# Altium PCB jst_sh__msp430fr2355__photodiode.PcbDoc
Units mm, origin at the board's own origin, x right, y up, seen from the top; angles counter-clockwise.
Board outline 56 x 30 mm, 2 copper layers (Top, Bottom), stack 0 mm thick; 17 components, 9 nets, 93 pads, 27 vias.
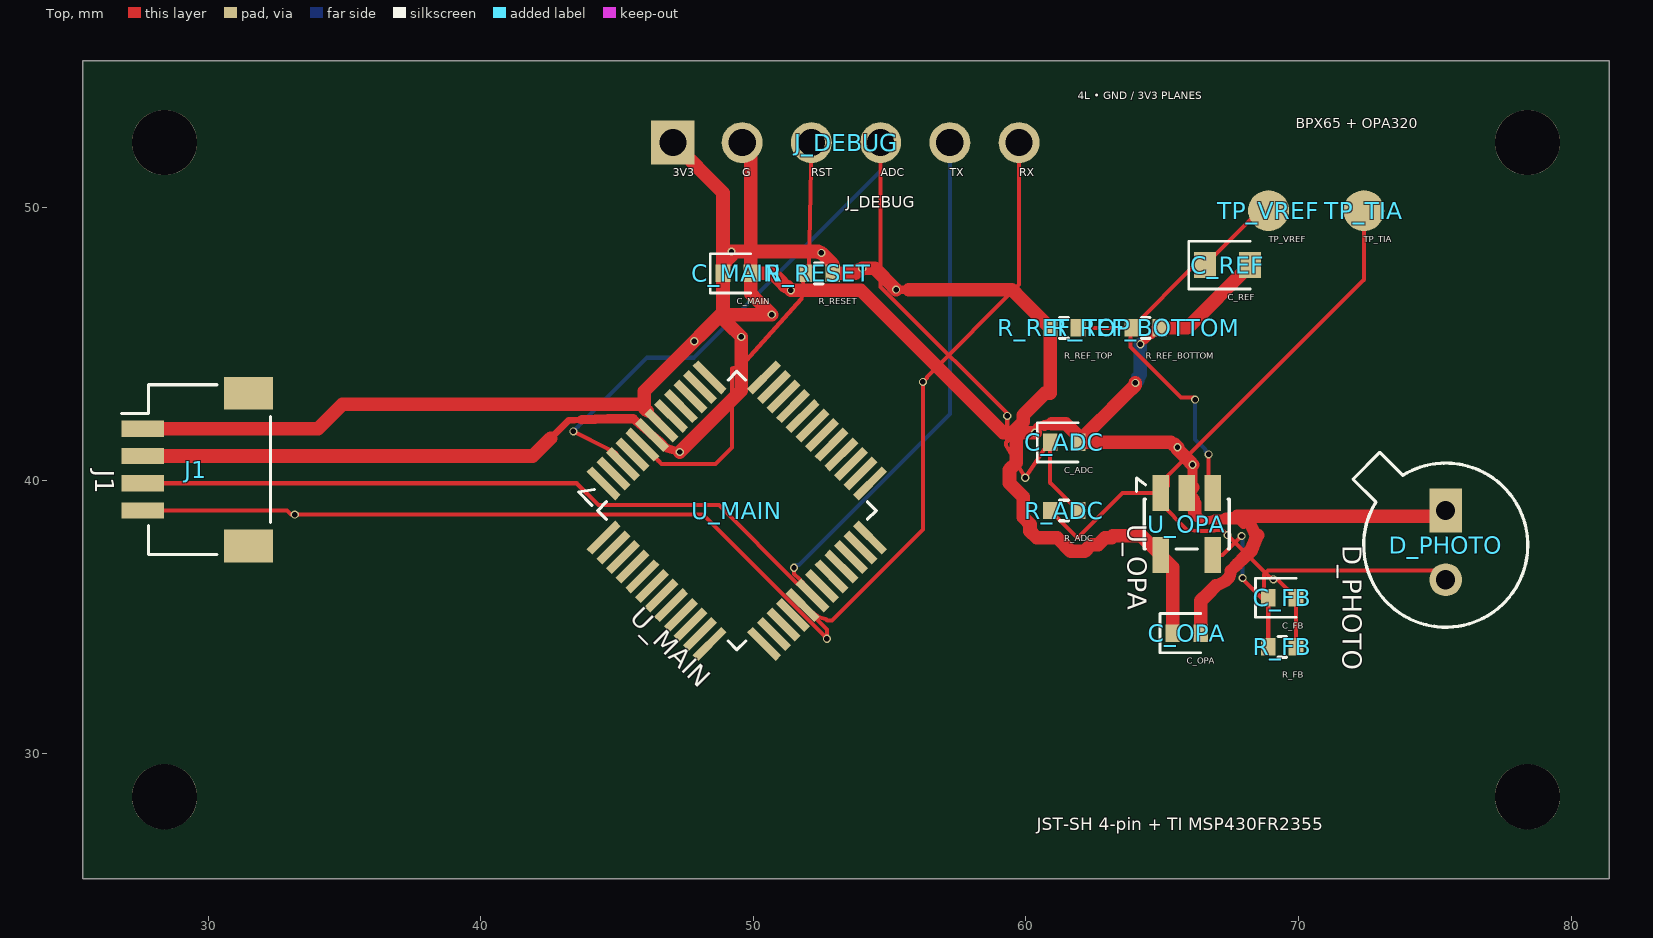
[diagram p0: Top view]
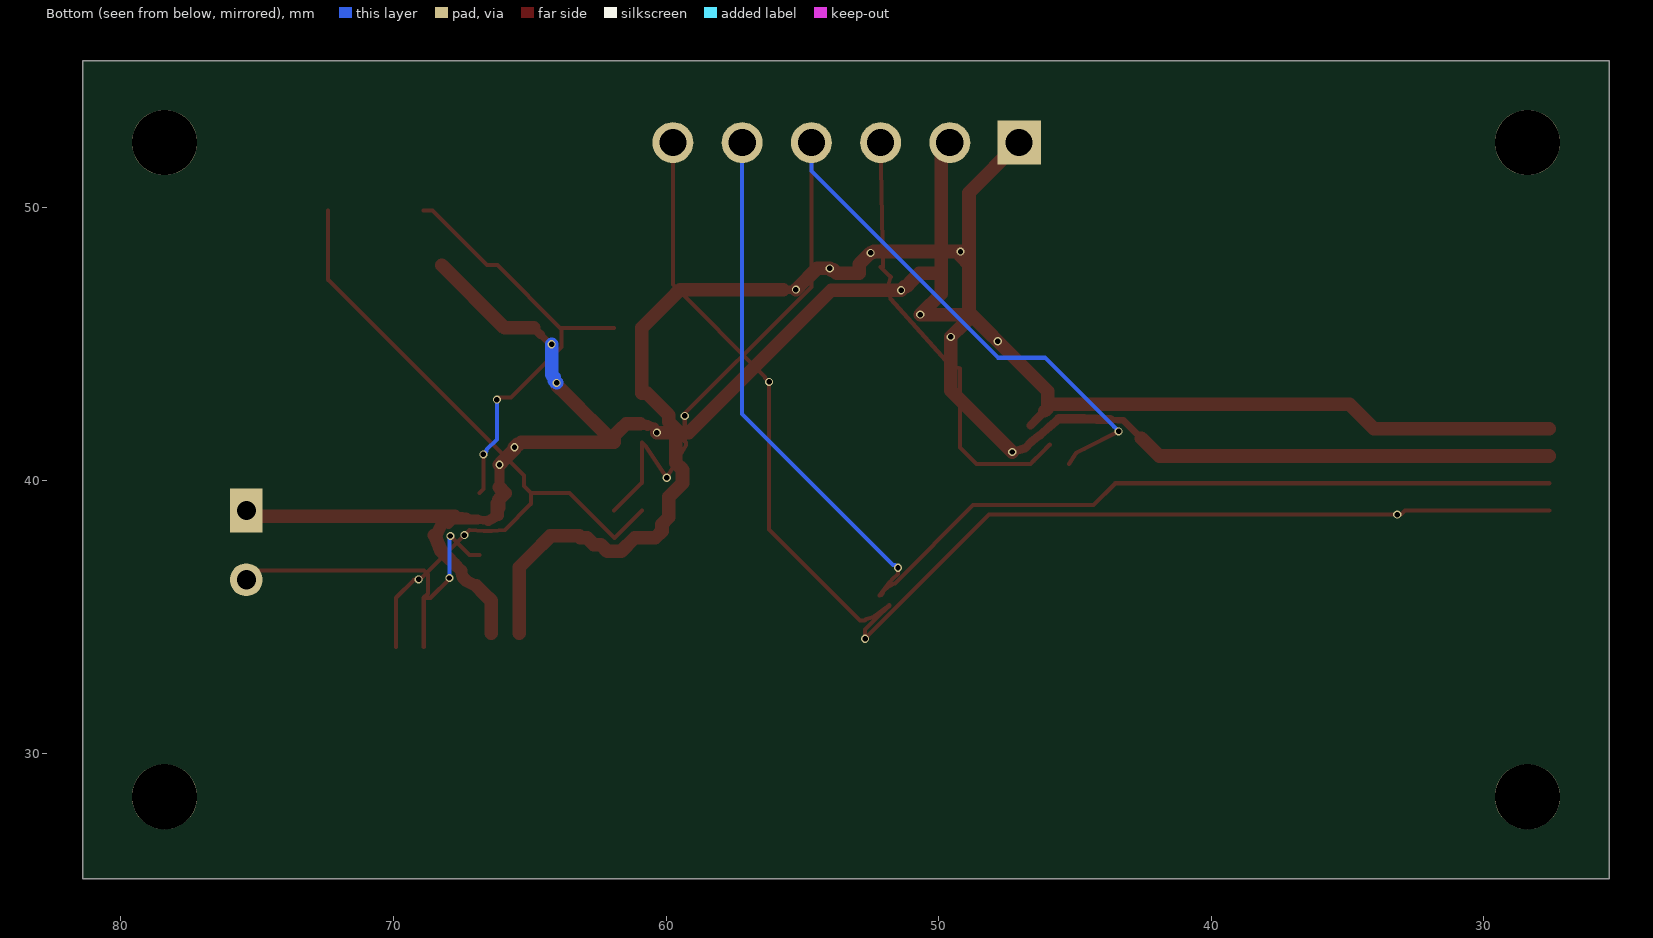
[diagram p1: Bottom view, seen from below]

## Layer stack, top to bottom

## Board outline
25.4,55.4 81.4,55.4 81.4,25.4 25.4,25.4

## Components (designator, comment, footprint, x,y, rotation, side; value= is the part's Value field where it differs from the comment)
C_ADC "" TSCIRCUIT-1.5600x0.6400mm 61.4,41.4 r0 top
C_FB "" TSCIRCUIT-1.5600x0.6400mm 69.4,35.7 r0 top
C_MAIN "" TSCIRCUIT-1.5600x0.6400mm 49.4,47.6 r0 top
C_OPA "" TSCIRCUIT-1.5600x0.6400mm 65.9,34.4 r0 top
C_REF "" TSCIRCUIT-2.4500x0.9500mm 67.4,47.9 r0 top
D_PHOTO "" TSCIRCUIT-1.2000x3.9400mm 75.4,37.73 r270 top
J1 "" TSCIRCUIT-5.5500x6.8000mm 29.6,40.4 r270 top
J_DEBUG "" TSCIRCUIT-14.2000x1.5000mm 53.4,52.4 r0 top
R_ADC "" TSCIRCUIT-1.5600x0.6400mm 61.4,38.9 r0 top
R_FB "" TSCIRCUIT-1.5600x0.6400mm 69.4,33.9 r0 top
R_REF_BOTTOM "" TSCIRCUIT-1.5600x0.6400mm 64.4,45.6 r0 top
R_REF_TOP "" TSCIRCUIT-1.5600x0.6400mm 61.4,45.6 r0 top
R_RESET "" TSCIRCUIT-1.5600x0.6400mm 52.4,47.6 r0 top
TP_TIA "" TSCIRCUIT-1.5000x1.5000mm 72.4,49.9 r0 top
TP_VREF "" TSCIRCUIT-1.5000x1.5000mm 68.9,49.9 r0 top
U_MAIN "" TSCIRCUIT-11.0309x11.0309mm 49.4,38.9 r315 top
U_OPA "" TSCIRCUIT-2.5000x3.6000mm 65.9,38.4 r270 top

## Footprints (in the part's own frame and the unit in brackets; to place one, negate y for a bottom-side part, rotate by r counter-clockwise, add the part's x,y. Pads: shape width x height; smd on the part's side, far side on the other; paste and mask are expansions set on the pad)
TSCIRCUIT-1.2000x3.9400mm [mm]
  rect 1.6x1.2 hole 0.7: 1(-1.17,0)
  round 1.2 hole 0.7: 2(1.37,0)
  silkscreen extent -3.3,-3.4 3.11,3.01
TSCIRCUIT-1.5000x1.5000mm [mm]
  round 1.5 smd: 1(0,0)
TSCIRCUIT-1.5600x0.6400mm [mm]
  rect 0.54x0.64 smd: 1(-0.51,0) 2(0.51,0)
  silkscreen extent -0.98,-0.72 0.51,0.72
TSCIRCUIT-2.4500x0.9500mm [mm]
  rect 0.8x0.95 smd: 1(-0.825,0) 2(0.825,0)
  silkscreen extent -1.43,-0.87 0.82,0.87
TSCIRCUIT-2.5000x3.6000mm [mm]
  rect 1.325x0.6 smd: 1(-1.138,-0.95) 2(-1.138,0) 3(-1.138,0.95) 4(1.137,0.95) 5(1.137,-0.95)
  silkscreen extent -1.69,-1.84 0.91,1.56
TSCIRCUIT-5.5500x6.8000mm [mm]
  rect 1.2x1.8 smd: 1(-2.8,1.875) 1(2.8,1.875)
  rect 0.6x1.55 smd: 1(-1.5,-2) 2(-0.5,-2) 3(0.5,-2) 4(1.5,-2)
  silkscreen extent -3.11,-2.77 3.11,2.69
TSCIRCUIT-11.0309x11.0309mm [mm]
  rect 1.475x0.3 smd: 1(-4.162,-2.75) 2(-4.162,-2.25) 3(-4.162,-1.75) 4(-4.162,-1.25) 5(-4.162,-0.75) 6(-4.162,-0.25) 7(-4.162,0.25) 8(-4.162,0.75) 9(-4.162,1.25) 10(-4.162,1.75) 11(-4.162,2.25) 12(-4.162,2.75) 25(4.162,2.75) 26(4.162,2.25) 27(4.163,1.75) 28(4.163,1.25) 29(4.162,0.75) 30(4.162,0.25) 31(4.163,-0.25) 32(4.163,-0.75) 33(4.162,-1.25) 34(4.162,-1.75) 35(4.163,-2.25) 36(4.163,-2.75)
  rect 0.3x1.475 smd: 13(-2.75,4.162) 14(-2.25,4.162) 15(-1.75,4.162) 16(-1.25,4.162) 17(-0.75,4.162) 18(-0.25,4.162) 19(0.25,4.162) 20(0.75,4.162) 21(1.25,4.162) 22(1.75,4.162) 23(2.25,4.162) 24(2.75,4.162) 37(2.75,-4.163) 38(2.25,-4.163) 39(1.75,-4.162) 40(1.25,-4.163) 41(0.75,-4.163) 42(0.25,-4.163) 43(-0.25,-4.162) 44(-0.75,-4.163) 45(-1.25,-4.163) 46(-1.75,-4.163) 47(-2.25,-4.162) 48(-2.75,-4.163)
  silkscreen extent -4.59,-3.63 3.61,3.61
TSCIRCUIT-14.2000x1.5000mm [mm]
  rect 1.6x1.6 hole 1: 1(-6.35,0)
  round 1.5 hole 1: 2(-3.81,0) 3(-1.27,0) 4(1.27,0) 5(3.81,0) 6(6.35,0)

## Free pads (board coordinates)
  round 2.4 hole 2.4 unplated: NPTH-1(28.4,28.4) NPTH-2(78.4,52.4) NPTH-3(78.4,28.4) NPTH-4(28.4,52.4)

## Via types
v1: diameter 0.3, hole 0.2, Top to Bottom, 27 vias

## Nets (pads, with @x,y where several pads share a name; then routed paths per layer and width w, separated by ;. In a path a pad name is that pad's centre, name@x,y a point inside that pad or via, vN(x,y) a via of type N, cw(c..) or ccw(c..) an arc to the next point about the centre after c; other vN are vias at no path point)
ADC_IN: C_ADC.1 J_DEBUG.4 R_ADC.2 U_MAIN.3 | length 37.5
  Top w0.15: v1(43.4,41.8) 44.658,41.162 44.953,41.015 U_MAIN.3 ; J_DEBUG.4 54.67,47.099 55.341,46.428 55.347,46.428 59.359,42.415 v1(59.315,42.371) 59.315,41.442 59.266,41.393 59.266,41.306 v1(59.975,40.1) 60.75,41.26 C_ADC.1 60.89,39.92 R_ADC.2
  Bottom w0.15: v1(43.4,41.8) 43.558,41.958 46.105,44.505 47.827,44.505 54.67,51.349 J_DEBUG.4
GND: C_ADC.2 C_MAIN.2 C_OPA.2 C_REF.2 D_PHOTO.1 J1.1@27.6,41.9 J_DEBUG.2 R_REF_BOTTOM.2 U_MAIN.7 U_OPA.2 | length 82.7
  Top w0.25: v1(64.2,45) 64.311,45.111 64.363,45.111 64.607,45.355
  Top w0.3: U_MAIN.7@46.373,42.282 U_MAIN.7
  Top w0.305: U_MAIN.7@46.114,42.544 U_MAIN.7@46.373,42.282
  Top w0.308: U_MAIN.7@46.115,42.544 46.353,42.304 U_MAIN.7
  Top w0.325: v1(60.337,41.759) 60.431,41.962 ; 64.607,45.355 R_REF_BOTTOM.2@64.852,45.6 ; 66.922,38.575 66.525,38.525 66.932,38.579 67.339,38.633
  Top w0.35: 60.431,41.962 60.688,42.024 ; U_OPA.2@66.111,39.749 66.111,40.162 v1(66.111,40.576)
  Top w0.375: U_OPA.2 66.079,39.358 66.258,39.179 66.258,38.687 66.525,38.525 66.15,38.713 ; 66.922,38.575 67.816,38.575 67.986,38.405 68.213,38.431
  Top w0.4: 60.688,42.024 60.944,42.086 ; U_OPA.2@66.138,39.012 66.15,38.713 ; 67.339,38.633 67.747,38.687
  Top w0.45: 46,42.8 46.072,42.587 U_MAIN.7@46.115,42.544 ; 66.964,36.138 67.327,36.317 67.473,36.463 67.517,36.691 67.764,36.938 ; 68.213,38.431 68.4,38.056
  Top w0.475: 45.85,42.803 45.853,42.806 46.113,42.544 ; 67.764,36.938 68.01,37.184 ; 68.4,38.056 68.494,37.994
  Top w0.5: J1.1@27.6,41.9 28.095,41.9 28.589,41.9 29.084,41.9 29.579,41.9 30.073,41.9 30.568,41.9 31.063,41.9 31.558,41.9 32.052,41.9 32.547,41.9 33.042,41.9 33.536,41.9 34.031,41.9 34.931,42.8 43.341,42.8 45.51,42.8 45.513,42.803 45.85,42.803 ; 46,42.8 46,43 46,43.276 v1(47.831,45.107) 47.832,45.108 48.158,45.434 48.485,45.761 48.811,46.087 49.277,46.087 49.742,46.087 50.208,46.087 v1(50.674,46.087) 50.619,46.142 50.619,46.144 50.382,46.38 50.146,46.616 49.91,46.852 49.91,47.226 C_MAIN.2 ; J_DEBUG.2 49.91,52.08 C_MAIN.2 ; v1(60.337,41.759) 59.166,41.759 59.025,41.9 53.943,46.982 v1(51.38,46.982) 51.259,47.103 51.204,47.103 50.956,47.352 50.707,47.6 50.309,47.6 C_MAIN.2 ; 60.944,42.086 61.224,42.086 61.464,42.086 61.65,41.9 61.91,41.64 C_ADC.2 ; v1(64.016,43.583) 64.016,43.506 63.665,43.155 63.314,42.804 62.963,42.453 62.612,42.102 62.261,41.751 C_ADC.2 ; R_REF_BOTTOM.2@64.852,45.6 R_REF_BOTTOM.2 65.925,45.6 C_REF.2 ; U_OPA.2@66.111,39.749 U_OPA.2 66.138,39.3 U_OPA.2@66.138,39.012 ; v1(66.111,40.576) 66.037,40.65 66.037,40.672 65.799,40.91 65.561,41.148 v1(65.561,41.224) 65.452,41.333 65.382,41.333 65.315,41.4 64.829,41.4 64.342,41.4 63.856,41.4 63.369,41.4 62.883,41.4 62.396,41.4 C_ADC.2 ; C_OPA.2 66.41,34.795 66.41,35.189 66.41,35.584 66.687,35.861 66.964,36.138 ; 67.747,38.687 68.243,38.687 68.739,38.687 69.235,38.687 69.731,38.687 70.227,38.687 70.723,38.687 71.219,38.687 71.715,38.687 72.211,38.687 72.707,38.687 73.203,38.687 73.699,38.687 74.195,38.687 74.691,38.687 75.187,38.687 D_PHOTO.1 ; 68.01,37.184 68.257,37.431 68.375,37.712 68.494,37.994
  Bottom w0.5: v1(64.016,43.583) 64.103,43.67 64.103,43.791 64.2,43.888 64.2,44.258 64.2,44.629 v1(64.2,45)
MAIN_RESET: J_DEBUG.3 R_RESET.1 U_MAIN.5 | length 16.4
  Top w0.15: U_MAIN.5 46.24,40.999 46.512,40.727 46.629,40.61 46.712,40.61 48.613,40.61 49.213,41.21 49.213,44.11 49.575,44.225 51.758,46.655 51.887,47.054 51.758,47.468 R_RESET.1 52.13,47.84 52.05,47.825 J_DEBUG.3
PD_SUM: C_FB.1 D_PHOTO.2 R_FB.1 U_OPA.4 | length 13.8
  Top w0.15: U_OPA.4 67.208,37.262 v1(67.911,37.965) ; v1(67.95,36.425) 67.941,36.416 67.941,36.395 68.636,35.7 C_FB.1 ; R_FB.1 C_FB.1 ; D_PHOTO.2 75.059,36.701 75.042,36.701 68.88,36.701 68.736,36.558 68.736,35.854 C_FB.1
  Bottom w0.15: v1(67.911,37.965) 67.92,37.956 67.92,37.911 67.95,37.881 v1(67.95,36.425)
TIA_OUT: C_FB.2 R_ADC.1 R_FB.2 TP_TIA.1 U_OPA.1 | length 27.2
  Top w0.15: R_ADC.1 61.896,37.894 63.539,39.538 U_OPA.1 ; R_FB.2 C_FB.2 69.238,36.372 v1(69.08,36.372) 69.005,36.447 68.953,36.447 v1(67.4,38) 67.354,38.046 67.214,38.186 66.681,38.146 66.411,38.15 65.913,38.186 64.95,39.149 U_OPA.1 ; TP_TIA.1 72.4,47.367 65.212,40.178 65.212,39.799 U_OPA.1
UART_MAIN_RX: J1.4 J_DEBUG.6 U_MAIN.32 | length 50.3
  Top w0.15: J1.4 32.888,38.9 33.038,38.75 v1(33.175,38.75) 48.157,38.75 52.616,34.29 52.616,34.277 v1(52.698,34.195) 52.698,34.542 52.414,34.826 52.303,34.936 52.127,35.113 51.972,35.26 51.937,35.286 51.897,35.324 51.825,35.375 U_MAIN.32 52.441,34.976 52.657,34.919 52.714,34.863 52.882,34.863 56.221,38.201 v1(56.221,43.617) 56.365,43.761 56.365,43.802 59.75,47.188 J_DEBUG.6
UART_MAIN_TX: J1.3 J_DEBUG.5 U_MAIN.31 | length 45.6
  Top w0.15: J1.3 43.521,39.9 44.325,39.096 48.744,39.096 51.61,36.23 51.853,36.1 52.024,35.942 52.041,35.899 52.059,35.853 52.1,35.8 U_MAIN.31 51.794,36.277 51.688,36.382 51.493,36.578 v1(51.493,36.8)
  Bottom w0.15: v1(51.493,36.8) 51.6,36.907 51.676,36.907 57.21,42.441 J_DEBUG.5
VCC_3V3: C_MAIN.1 C_OPA.1 J1.2 J_DEBUG.1 R_REF_TOP.1 R_RESET.2 U_MAIN.6 U_OPA.5 | length 65.3
  Top w0.25: 42.564,41.553 42.891,41.879 43.217,42.205 43.71,42.229
  Top w0.3: U_MAIN.6@45.934,41.971 U_MAIN.6
  Top w0.312: 45.588,42.275 U_MAIN.6@45.934,41.971 ; U_MAIN.6 46.593,41.431 46.838,41.181 v1(47.301,41.046) ; v1(55.236,47.004) 55.708,47.004
  Top w0.35: 43.71,42.229 44.203,42.254 44.664,42.261 45.126,42.268 45.588,42.275
  Top w0.5: J1.2 28.094,40.9 28.587,40.9 29.081,40.9 29.574,40.9 30.068,40.9 30.561,40.9 31.055,40.9 31.548,40.9 32.042,40.9 32.535,40.9 33.029,40.9 33.522,40.9 34.016,40.9 34.509,40.9 35.003,40.9 35.496,40.9 35.99,40.9 36.483,40.9 36.977,40.9 37.47,40.9 37.964,40.9 38.457,40.9 38.951,40.9 39.444,40.9 39.938,40.9 40.431,40.9 40.925,40.9 41.418,40.9 41.912,40.9 42.238,41.226 42.564,41.553 ; J_DEBUG.1 48.89,50.56 C_MAIN.1 ; v1(47.301,41.046) 47.311,41.056 47.632,41.377 47.953,41.698 48.273,42.018 48.594,42.339 48.915,42.66 49.236,42.981 49.557,43.302 49.557,43.794 49.557,44.285 49.557,44.777 v1(49.557,45.269) 49.481,45.345 49.185,45.641 48.89,45.936 48.89,46.352 48.89,46.768 48.89,47.184 C_MAIN.1 ; v1(55.236,47.004) 55.192,47.048 54.948,47.292 54.703,47.537 54.459,47.781 v1(53.998,47.781) 53.942,47.725 53.858,47.725 53.734,47.6 53.322,47.6 R_RESET.2 52.91,47.94 v1(52.497,48.353) 52.493,48.356 52.431,48.356 52.387,48.4 51.932,48.4 51.477,48.4 51.021,48.4 50.566,48.4 50.111,48.4 49.655,48.4 v1(49.2,48.4) 49.187,48.387 49.187,48.227 48.89,47.93 C_MAIN.1 ; 55.708,47.004 56.18,47.004 56.653,47.004 57.125,47.004 57.597,47.004 58.069,47.004 58.542,47.004 59.014,47.004 59.486,47.004 59.837,46.653 60.188,46.302 60.539,45.951 R_REF_TOP.1 60.89,43.213 60.713,43.213 59.9,42.4 59.9,42.15 59.65,41.9 59.65,40.65 59.4,40.4 59.4,39.9 59.9,39.4 59.9,38.65 60.15,38.4 60.15,38.15 60.4,37.9 61.15,37.9 61.65,37.4 62.15,37.4 62.4,37.65 62.65,37.65 62.9,37.9 63.15,37.9 63.15,37.933 63.185,37.968 64.244,37.968 U_OPA.5 65.39,36.822 C_OPA.1
VREF_0V5: C_REF.1 R_REF_BOTTOM.1 R_REF_TOP.2 TP_VREF.1 U_OPA.3 | length 16.4
  Top w0.15: R_REF_TOP.2 R_REF_BOTTOM.1 ; v1(66.207,42.971) 66.131,43.047 66.063,43.047 65.685,43.047 63.832,44.9 63.832,45.542 R_REF_BOTTOM.1 ; v1(66.703,40.96) 66.703,39.684 U_OPA.3 ; TP_VREF.1 68.575,49.9 C_REF.1 66.19,47.9 R_REF_BOTTOM.1
  Bottom w0.15: v1(66.207,42.971) 66.207,41.511 66.588,41.13 66.588,41.075 v1(66.703,40.96)
pads on no net: J1.1@31.475,37.6 J1.1@31.475,43.2 U_MAIN.1 U_MAIN.2 U_MAIN.4 U_MAIN.8 U_MAIN.9 U_MAIN.10 U_MAIN.11 U_MAIN.12 U_MAIN.13 U_MAIN.14 U_MAIN.15 U_MAIN.16 U_MAIN.17 U_MAIN.18 U_MAIN.19 U_MAIN.20 U_MAIN.21 U_MAIN.22 U_MAIN.23 U_MAIN.24 U_MAIN.25 U_MAIN.26 U_MAIN.27 U_MAIN.28 U_MAIN.29 U_MAIN.30 U_MAIN.33 U_MAIN.34 U_MAIN.35 U_MAIN.36 U_MAIN.37 U_MAIN.38 U_MAIN.39 U_MAIN.40 U_MAIN.41 U_MAIN.42 U_MAIN.43 U_MAIN.44 U_MAIN.45 U_MAIN.46 U_MAIN.47 U_MAIN.48

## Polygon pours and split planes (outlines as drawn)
GND on Mid1 (solid): 81.1,55.1 25.7,55.1 25.7,25.7 81.1,25.7
VCC_3V3 on Mid2 (solid): 81.1,55.1 25.7,55.1 25.7,25.7 81.1,25.7

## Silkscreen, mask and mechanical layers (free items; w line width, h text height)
Top Overlay:
  text "4L • GND / 3V3 PLANES" at 61.9,53.9 h0.48
  text "BPX65 + OPA320" at 69.9,52.8 h0.65
  text "JST-SH 4-pin + TI MSP430FR2355" at 60.4,27 h0.78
